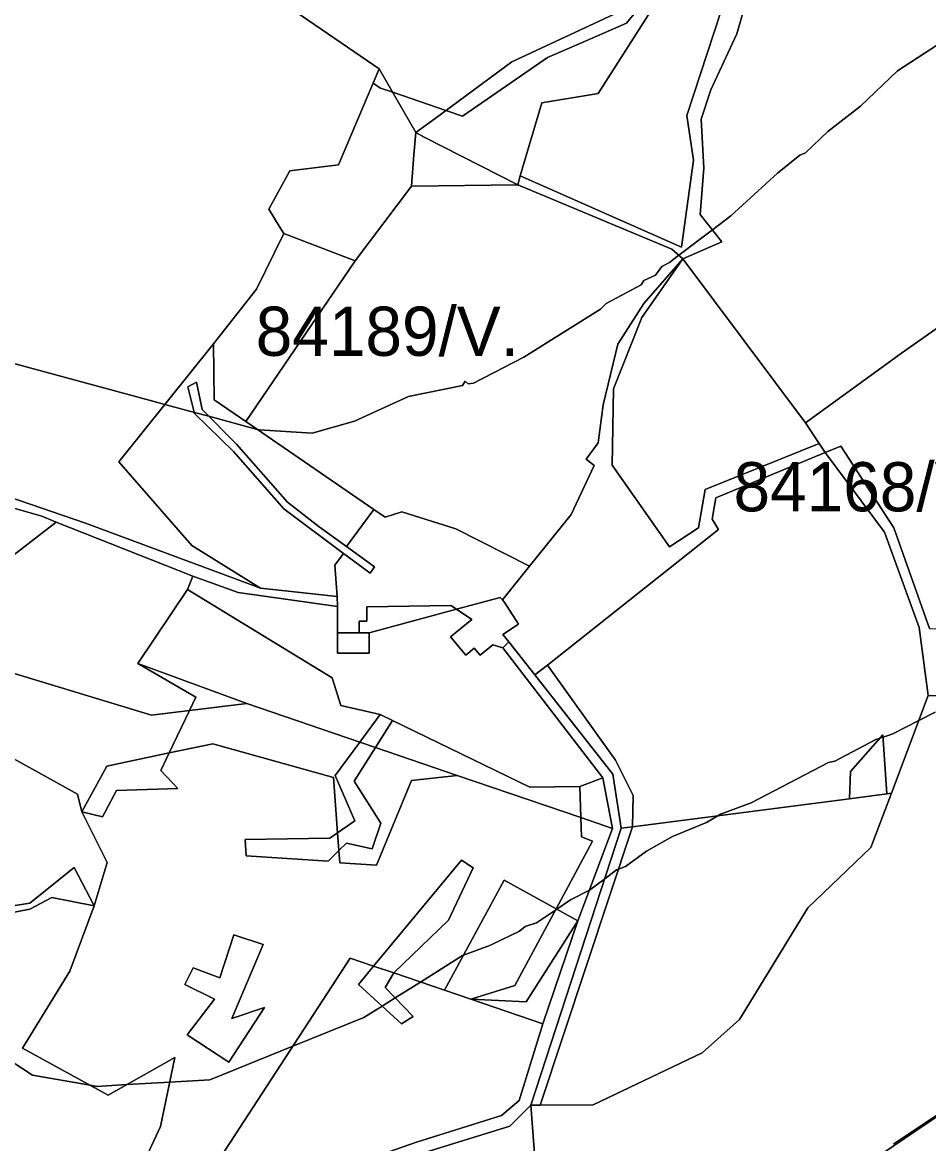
# Model space of a CAD drawing. Extents: x -477304 to -465429, y -1159113 to -1149210.
# Drawn here: x -472634.3 to -472357.9, y -1156987 to -1156645.1 of the extents above; entities that cross this region are included whole.
import ezdxf

# ---------------------------------------------------------------- set-up
doc = ezdxf.new("R2010")
doc.units = 0
for name, color, linetype in [('BPEJ_s', 7, 'Continuous'), ('ostatni_s', 7, 'Continuous'), ('PUPFL_s', 7, 'Continuous'), ('trav_porost_s', 7, 'Continuous'), ('zahrada_s', 7, 'Continuous')]:
    doc.layers.add(name, color=color, linetype=linetype)

msp = doc.modelspace()

# ---------------------------------------------------------------- linework, layer by layer
at = {"layer": 'BPEJ_s'}
for points in [[(-472441.7, -1156635.08), (-472450.07, -1156645.39), (-472463.76, -1156651.33), (-472474.1, -1156655.82), (-472486.64, -1156664.49), (-472500, -1156673.73), (-472505.12, -1156671.99), (-472521.34, -1156666.45), (-472525.09, -1156665.17), (-472526.28, -1156664.38), (-472527.3, -1156663.7), (-472525.43, -1156659.31), (-472554.72, -1156639.26)], [(-472554.72, -1156639.26), (-472525.43, -1156659.31), (-472527.3, -1156663.7), (-472526.28, -1156664.38), (-472525.09, -1156665.17), (-472521.34, -1156666.45), (-472505.12, -1156671.99), (-472500, -1156673.73), (-472486.64, -1156664.49), (-472474.1, -1156655.82), (-472463.76, -1156651.33), (-472450.07, -1156645.39), (-472441.7, -1156635.08)], [(-472662.1, -1156742.37), (-472594.52, -1156760.62), (-472590.83, -1156761.62), (-472581.83, -1156764.06), (-472577.42, -1156765.25), (-472562.69, -1156769.24), (-472562.09, -1156769.4), (-472545.87, -1156770.42), (-472533.03, -1156766.7), (-472516.48, -1156759.27), (-472500, -1156755.83), (-472499.2, -1156754.5), (-472498.35, -1156755.35), (-472496.64, -1156755.14), (-472481.33, -1156747.27), (-472457.94, -1156732.59), (-472456.24, -1156730.89), (-472445.6, -1156725.15), (-472444.75, -1156723.87), (-472441.14, -1156722.17), (-472439.22, -1156719.62), (-472436.96, -1156718.38), (-472434.05, -1156716.17), (-472423.83, -1156708.4), (-472418.17, -1156704.09), (-472403.92, -1156691.12), (-472397.11, -1156685.59), (-472395.41, -1156684.95), (-472388.6, -1156678.36), (-472378.61, -1156670.7), (-472367.34, -1156659.86), (-472355.21, -1156651.99)], [(-472355.21, -1156651.99), (-472367.34, -1156659.86), (-472378.61, -1156670.7), (-472388.6, -1156678.36), (-472395.41, -1156684.95), (-472397.11, -1156685.59), (-472403.92, -1156691.12), (-472418.17, -1156704.09), (-472423.83, -1156708.4), (-472434.05, -1156716.17), (-472436.96, -1156718.38), (-472439.22, -1156719.62), (-472441.14, -1156722.17), (-472444.75, -1156723.87), (-472445.6, -1156725.15), (-472456.24, -1156730.89), (-472457.94, -1156732.59), (-472481.33, -1156747.27), (-472496.64, -1156755.14), (-472498.35, -1156755.35), (-472499.2, -1156754.5), (-472500, -1156755.83), (-472516.48, -1156759.27), (-472533.03, -1156766.7), (-472545.87, -1156770.42), (-472562.09, -1156769.4), (-472562.69, -1156769.24), (-472577.42, -1156765.25), (-472581.83, -1156764.06), (-472590.83, -1156761.62), (-472594.52, -1156760.62), (-472662.1, -1156742.37)], [(-472116.37, -1156762.45), (-472135.94, -1156774.49), (-472198.26, -1156835.74), (-472215.96, -1156868.96), (-472217.19, -1156871.26), (-472218.74, -1156885.27), (-472220.16, -1156898.05), (-472220.17, -1156899.22), (-472220.24, -1156910.32), (-472246.54, -1156919.54), (-472276.74, -1156936.97), (-472303.41, -1156955.05), (-472309.06, -1156958.88), (-472333.73, -1156964.62), (-472337.14, -1156966.32), (-472354.15, -1156977.59), (-472368.61, -1156987.17)], [(-472135.94, -1156774.49), (-472198.26, -1156835.74), (-472215.96, -1156868.96), (-472217.19, -1156871.26), (-472218.74, -1156885.27), (-472220.16, -1156898.05), (-472220.17, -1156899.22), (-472220.24, -1156910.32), (-472246.54, -1156919.54), (-472276.74, -1156936.97), (-472303.41, -1156955.05), (-472309.06, -1156958.88), (-472333.73, -1156964.62), (-472337.14, -1156966.32), (-472354.15, -1156977.59), (-472368.61, -1156987.17)], [(-472355.85, -1156855.52), (-472360.86, -1156858.06), (-472368.83, -1156862.11), (-472370.52, -1156862.68), (-472371.78, -1156863.1), (-472372.19, -1156863.23), (-472372.7, -1156863.4), (-472373.93, -1156863.81), (-472386.48, -1156870.41), (-472388.39, -1156870.83), (-472412, -1156883.17), (-472421.36, -1156886.57), (-472422.19, -1156887.07), (-472425.61, -1156889.12), (-472436.03, -1156893.38), (-472443.9, -1156897.84), (-472450.28, -1156902.52), (-472452.45, -1156903.35), (-472453.05, -1156903.58), (-472456.68, -1156906.29), (-472461.32, -1156909.73), (-472467.08, -1156912.73), (-472471.28, -1156915.56), (-472471.67, -1156915.82), (-472477.5, -1156919.75), (-472480.91, -1156920.81), (-472482.61, -1156922.3), (-472491.11, -1156926.34), (-472492.06, -1156926.69), (-472499.7, -1156929.55), (-472500, -1156929.67), (-472512.87, -1156937.77), (-472520.56, -1156942.6), (-472524.57, -1156945.12), (-472530.16, -1156948.64), (-472551.8, -1156957.36), (-472577.12, -1156967.56), (-472589.32, -1156968.28), (-472602.4, -1156969.05), (-472611.59, -1156969.59)], [(-472422.19, -1156887.07), (-472421.36, -1156886.57), (-472412, -1156883.17), (-472388.39, -1156870.83), (-472386.48, -1156870.41), (-472373.93, -1156863.81), (-472372.7, -1156863.4), (-472372.19, -1156863.23), (-472371.78, -1156863.1), (-472370.52, -1156862.68), (-472368.83, -1156862.11), (-472360.86, -1156858.06), (-472355.85, -1156855.52)], [(-472640.98, -1156959.79), (-472631.18, -1156966.21), (-472613.63, -1156969.24), (-472611.59, -1156969.59), (-472602.4, -1156969.05), (-472589.32, -1156968.28), (-472577.12, -1156967.56), (-472551.8, -1156957.36), (-472530.16, -1156948.64), (-472524.57, -1156945.12), (-472520.56, -1156942.6), (-472512.87, -1156937.77), (-472500, -1156929.67), (-472499.7, -1156929.55), (-472492.06, -1156926.69), (-472491.11, -1156926.34), (-472482.61, -1156922.3), (-472480.91, -1156920.81), (-472477.5, -1156919.75), (-472471.67, -1156915.82), (-472471.28, -1156915.56), (-472467.08, -1156912.73), (-472461.32, -1156909.73), (-472456.68, -1156906.29), (-472453.05, -1156903.58), (-472452.45, -1156903.35), (-472450.28, -1156902.52), (-472443.9, -1156897.84), (-472436.03, -1156893.38), (-472425.61, -1156889.12), (-472422.19, -1156887.07)], [(-472611.59, -1156969.59), (-472613.63, -1156969.24), (-472631.18, -1156966.21), (-472640.98, -1156959.79)]]:
    msp.add_lwpolyline(points, dxfattribs=at)
at = {"layer": 'ostatni_s'}
for points in [[(-472532.82, -1156717.86), (-472566.14, -1156766.88), (-472575.82, -1156760.24), (-472576.01, -1156743.14), (-472562.87, -1156726.46), (-472554.55, -1156709.55)], [(-472583.78, -1156756.26), (-472581.17, -1156754.82), (-472579.43, -1156763.23), (-472568.95, -1156773.78), (-472553.46, -1156791.45), (-472543.79, -1156799), (-472535.43, -1156805), (-472526.87, -1156811.15), (-472528.16, -1156813.09), (-472533.27, -1156809.36), (-472536.38, -1156807.08), (-472554.52, -1156793.52), (-472569.91, -1156775.96), (-472581.75, -1156764.37)], [(-472357.62, -1156830), (-472352.97, -1156830.05), (-472351.8, -1156850.64), (-472357.97, -1156850.39), (-472360.81, -1156829.71), (-472371.34, -1156800.62), (-472389.42, -1156776.33), (-472384.69, -1156774.37), (-472368.5, -1156799.23)], [(-472531.53, -1156827.77), (-472531.54, -1156831.27), (-472538.14, -1156831.25), (-472538.12, -1156823.31), (-472538.32, -1156820.17), (-472539, -1156810.66), (-472536.38, -1156807.08), (-472533.27, -1156809.36), (-472528.16, -1156813.09), (-472526.87, -1156811.15), (-472535.43, -1156805), (-472527.1, -1156793.63), (-472523.6, -1156796.04), (-472518.57, -1156794.35), (-472502.12, -1156799.6), (-472479.61, -1156811), (-472487.86, -1156821.27), (-472488.56, -1156820.47), (-472501.86, -1156824.07), (-472503.6, -1156822.91), (-472529.23, -1156823.34), (-472529.25, -1156827.78)], [(-472528.54, -1156831.28), (-472531.54, -1156831.27), (-472531.53, -1156827.77), (-472529.25, -1156827.78), (-472529.23, -1156823.34), (-472503.6, -1156822.91), (-472501.86, -1156824.07)], [(-472499.07, -1156838.1), (-472503.66, -1156832.52), (-472497.18, -1156827.18), (-472501.86, -1156824.07), (-472488.56, -1156820.47), (-472487.86, -1156821.27), (-472487.34, -1156821.85), (-472482.93, -1156828.68), (-472487.71, -1156831.76), (-472485.9, -1156834.06), (-472487.76, -1156835.82), (-472490.82, -1156834.9), (-472494.67, -1156838.07), (-472496.44, -1156835.93)], [(-472528.56, -1156837.53), (-472538.16, -1156837.5), (-472538.14, -1156831.25), (-472531.54, -1156831.27), (-472528.54, -1156831.28)]]:
    msp.add_lwpolyline(points, close=True, dxfattribs=at)
for points in [[(-472648.53, -1156786.33), (-472615, -1156797.87), (-472561.62, -1156817.71), (-472538.32, -1156820.17), (-472538.12, -1156823.31), (-472568.42, -1156819.04), (-472582.32, -1156813.98), (-472624, -1156797.56), (-472628.39, -1156795.71), (-472647.71, -1156790.18)], [(-472548.47, -1156998.65), (-472514.05, -1156986.63), (-472488.17, -1156978.52), (-472482.8, -1156973.95), (-472475.52, -1156950.49), (-472464.82, -1156919.14), (-472454.27, -1156890.91), (-472457.23, -1156875.51), (-472487.76, -1156835.82), (-472485.9, -1156834.06), (-472477.97, -1156844.13), (-472454.24, -1156874.36), (-472451.66, -1156890.88), (-472479.18, -1156975.3), (-472485.63, -1156981.69), (-472512.56, -1156990.09)]]:
    msp.add_lwpolyline(points, dxfattribs=at)
at = {"layer": 'PUPFL_s'}
for points in [[(-472436.06, -1156618.15), (-472452.46, -1156641.98), (-472485.02, -1156657.15), (-472508.39, -1156674.4), (-472514.3, -1156678.76), (-472525.43, -1156659.31), (-472554.72, -1156639.26), (-472590.4, -1156625.83), (-472583.95, -1156534.35), (-472531.75, -1156522.28), (-472529.41, -1156526.79), (-472515.08, -1156528.87), (-472489.81, -1156543.28), (-472462.88, -1156546.83), (-472460.93, -1156553.43), (-472447.67, -1156591.44), (-472437.2, -1156615.54)], [(-472508.39, -1156674.4), (-472485.02, -1156657.15), (-472452.46, -1156641.98), (-472436.06, -1156618.15), (-472400.56, -1156584.81), (-472397.11, -1156583.52), (-472394.76, -1156582.64), (-472393.84, -1156583.61), (-472388.14, -1156589.63), (-472394.29, -1156598.74), (-472402.85, -1156601.83), (-472408.83, -1156604), (-472410.88, -1156604.47), (-472429.76, -1156618.89), (-472439.49, -1156636.61), (-472458.68, -1156666.86), (-472475.87, -1156669.7), (-472482.41, -1156691.96), (-472483.21, -1156694.68), (-472511.7, -1156680.09), (-472514.3, -1156678.76)], [(-472532.82, -1156717.86), (-472554.55, -1156709.55), (-472555.97, -1156707.24), (-472559.13, -1156702.14), (-472552.69, -1156690.37), (-472537.88, -1156688.58), (-472525.43, -1156659.31), (-472514.3, -1156678.76), (-472514.85, -1156685.5), (-472515.63, -1156695.03)], [(-472483.21, -1156694.68), (-472515.63, -1156695.03), (-472514.85, -1156685.5), (-472514.3, -1156678.76), (-472511.7, -1156680.09)], [(-472706.78, -1156867.02), (-472715.43, -1156871.86), (-472717.75, -1156866.96), (-472665.8, -1156829.71), (-472646.02, -1156814.49), (-472637.12, -1156843.61), (-472594.91, -1156856.41), (-472583.36, -1156855), (-472589.5, -1156867.9), (-472608.5, -1156871.93), (-472616.12, -1156885.89), (-472617.48, -1156880.47), (-472647.02, -1156864.09), (-472671.49, -1156885.37), (-472682.72, -1156870.62), (-472696.04, -1156876.51)], [(-472476.37, -1156975.29), (-472460.19, -1156975.26), (-472426.99, -1156959.38), (-472415.58, -1156949.24), (-472394.67, -1156915.11), (-472375.46, -1156896.76), (-472369.2, -1156880.22), (-472357.97, -1156850.39), (-472351.8, -1156850.64), (-472270.77, -1156853.98), (-472230.8, -1156865.95), (-472215.62, -1156866.51), (-472221.16, -1156906.32), (-472251.67, -1156919.39), (-472287.03, -1156938.71), (-472307.14, -1156958.77), (-472336.68, -1156966.17), (-472382.8, -1156997.43), (-472414.59, -1157035.96), (-472473.75, -1157053.08), (-472475.82, -1157019.69), (-472479.18, -1156975.3)], [(-472583.36, -1156855), (-472565.83, -1156852.87), (-472531.4, -1156864.64), (-472538.92, -1156874.83), (-472532.92, -1156888.62), (-472538.15, -1156892.29), (-472539.42, -1156875.41), (-472576.23, -1156865.09), (-472589.5, -1156867.9)], [(-472537.75, -1156897.66), (-472538.15, -1156892.29), (-472532.92, -1156888.62), (-472538.92, -1156874.83), (-472531.4, -1156864.64), (-472526.61, -1156866.28), (-472533.1, -1156876.57), (-472524.98, -1156889.34), (-472527.61, -1156897.18), (-472535.45, -1156895.39)], [(-472537.46, -1156901.45), (-472537.75, -1156897.66), (-472535.45, -1156895.39), (-472527.61, -1156897.18), (-472524.98, -1156889.34), (-472533.1, -1156876.57), (-472526.61, -1156866.28), (-472501.7, -1156874.79), (-472515.56, -1156876.3), (-472526.3, -1156902.18)], [(-472375.46, -1156896.76), (-472394.67, -1156915.11), (-472415.58, -1156949.24), (-472426.99, -1156959.38), (-472460.19, -1156975.26), (-472476.37, -1156975.29), (-472448.15, -1156890.43), (-472382.04, -1156881.88), (-472370.59, -1156880.4), (-472369.2, -1156880.22)], [(-472479.18, -1156975.3), (-472451.66, -1156890.88), (-472448.15, -1156890.43), (-472476.37, -1156975.29)], [(-472632.01, -1156915.58), (-472656.6, -1156920.34), (-472657.25, -1156917.68), (-472632.02, -1156913.73), (-472618.53, -1156902.87), (-472612.42, -1156914.59), (-472625.27, -1156912.02)], [(-472707.28, -1157125.61), (-472723.28, -1157131.37), (-472760.71, -1157130.4), (-472753.24, -1157123.49), (-472750.8, -1157125.46), (-472716.75, -1157116.55), (-472705.79, -1157108.09), (-472683.02, -1157097.79), (-472646.35, -1157067.59), (-472593.93, -1157027.42), (-472543.78, -1157001.28), (-472512.56, -1156990.09), (-472485.63, -1156981.69), (-472479.18, -1156975.3), (-472475.82, -1157019.69), (-472473.75, -1157053.08), (-472499.35, -1157059.5), (-472542.32, -1157097.74), (-472575.02, -1157101.39), (-472662.17, -1157111.11), (-472693.12, -1157120.63)]]:
    msp.add_lwpolyline(points, close=True, dxfattribs=at)
for points in [[(-472647.02, -1156864.09), (-472617.48, -1156880.47), (-472616.12, -1156885.89), (-472608.39, -1156901.31), (-472612.42, -1156914.59), (-472618.53, -1156902.87), (-472632.02, -1156913.73), (-472657.25, -1156917.68)], [(-472656.6, -1156920.34), (-472632.01, -1156915.58), (-472625.27, -1156912.02), (-472612.42, -1156914.59), (-472619.78, -1156934.51), (-472634.24, -1156957.92), (-472608.12, -1156972.26), (-472587.78, -1156960.84), (-472592.11, -1156981.8), (-472613.67, -1157028.18)], [(-472382.8, -1156997.43), (-472336.68, -1156966.17)]]:
    msp.add_lwpolyline(points, dxfattribs=at)
at = {"layer": 'trav_porost_s'}
for points in [[(-472227.65, -1156648.59), (-472366.12, -1156746.03), (-472395.47, -1156767.24), (-472432.86, -1156717.23), (-472420.96, -1156712.01), (-472427.52, -1156703.76), (-472426.47, -1156689.61), (-472427.29, -1156674.6), (-472424.28, -1156665.71), (-472416.34, -1156648.59), (-472402.85, -1156601.83), (-472394.29, -1156598.74), (-472391.67, -1156597.79), (-472373.99, -1156587.03), (-472357.34, -1156582.81)], [(-472660.7, -1156596.17), (-472629.98, -1156612.77), (-472590.4, -1156625.83), (-472554.72, -1156639.26), (-472525.43, -1156659.31), (-472537.88, -1156688.58), (-472552.69, -1156690.37), (-472559.13, -1156702.14), (-472555.97, -1156707.24), (-472554.55, -1156709.55), (-472562.87, -1156726.46), (-472576.01, -1156743.14), (-472604.86, -1156779.11), (-472582.6, -1156804.65), (-472561.62, -1156817.71), (-472615, -1156797.87), (-472648.53, -1156786.33)], [(-472357.62, -1156830), (-472368.5, -1156799.23), (-472384.69, -1156774.37), (-472389.42, -1156776.33), (-472391.29, -1156773.52), (-472395.47, -1156767.24), (-472366.12, -1156746.03), (-472227.65, -1156648.59)], [(-472613.67, -1157028.18), (-472592.11, -1156981.8), (-472587.78, -1156960.84), (-472608.12, -1156972.26), (-472634.24, -1156957.92), (-472619.78, -1156934.51), (-472612.42, -1156914.59), (-472608.39, -1156901.31), (-472616.12, -1156885.89), (-472609.87, -1156887.35), (-472605.6, -1156879.37), (-472586.85, -1156878.75), (-472592.04, -1156873.23), (-472589.5, -1156867.9), (-472576.23, -1156865.09), (-472539.42, -1156875.41), (-472538.15, -1156892.29), (-472540.49, -1156893.94), (-472566.35, -1156894.33), (-472566.07, -1156899.31), (-472540.99, -1156900.88), (-472537.75, -1156897.66), (-472537.46, -1156901.45), (-472526.3, -1156902.18), (-472515.56, -1156876.3), (-472501.7, -1156874.79), (-472463.95, -1156887.61), (-472463.76, -1156893.52), (-472460.37, -1156894.86), (-472471.47, -1156915.45), (-472487.29, -1156906.69), (-472505.51, -1156940.26), (-472520.99, -1156935.02), (-472504.28, -1156918.96), (-472496.82, -1156902.94), (-472500.35, -1156900.61), (-472527.17, -1156932.93), (-472534.32, -1156930.51), (-472594.99, -1157023.68)]]:
    msp.add_lwpolyline(points, dxfattribs=at)
for points in [[(-472416.34, -1156648.59), (-472424.28, -1156665.71), (-472427.29, -1156674.6), (-472426.47, -1156689.61), (-472427.52, -1156703.76), (-472420.96, -1156712.01), (-472432.86, -1156717.23), (-472436.15, -1156714.29), (-472483.21, -1156694.68), (-472482.41, -1156691.96), (-472433.2, -1156713.71), (-472429.61, -1156687.16), (-472431.62, -1156673.53), (-472408.83, -1156604), (-472402.85, -1156601.83)], [(-472429.76, -1156618.89), (-472410.88, -1156604.47), (-472408.83, -1156604), (-472431.62, -1156673.53), (-472429.61, -1156687.16), (-472433.2, -1156713.71), (-472482.41, -1156691.96), (-472475.87, -1156669.7), (-472458.68, -1156666.86), (-472439.49, -1156636.61)], [(-472479.61, -1156811), (-472502.12, -1156799.6), (-472518.57, -1156794.35), (-472523.6, -1156796.04), (-472527.1, -1156793.63), (-472566.14, -1156766.88), (-472532.82, -1156717.86), (-472515.63, -1156695.03), (-472483.21, -1156694.68), (-472436.15, -1156714.29), (-472432.86, -1156717.23), (-472444.69, -1156730.83), (-472452.68, -1156743.3), (-472457.18, -1156761.73), (-472458.62, -1156773.31), (-472462.3, -1156778.28), (-472459.86, -1156780.26), (-472466.92, -1156795.2)], [(-472428.06, -1156799.22), (-472426.01, -1156787.57), (-472391.29, -1156773.52), (-472389.42, -1156776.33), (-472422.75, -1156790.15), (-472423.88, -1156796.63), (-472421.99, -1156799.75), (-472474.13, -1156841.1), (-472477.97, -1156844.13), (-472485.9, -1156834.06), (-472487.71, -1156831.76), (-472482.93, -1156828.68), (-472487.34, -1156821.85), (-472487.86, -1156821.27), (-472479.61, -1156811), (-472466.92, -1156795.2), (-472459.86, -1156780.26), (-472462.3, -1156778.28), (-472458.62, -1156773.31), (-472457.18, -1156761.73), (-472452.68, -1156743.3), (-472444.69, -1156730.83), (-472432.86, -1156717.23), (-472445.34, -1156735.08), (-472453.96, -1156756.86), (-472454.41, -1156780.18), (-472436.92, -1156805.09)], [(-472453.96, -1156756.86), (-472445.34, -1156735.08), (-472432.86, -1156717.23), (-472395.47, -1156767.24), (-472391.29, -1156773.52), (-472426.01, -1156787.57), (-472428.06, -1156799.22), (-472436.92, -1156805.09), (-472454.41, -1156780.18)], [(-472647.71, -1156790.18), (-472628.39, -1156795.71), (-472624, -1156797.56), (-472646.02, -1156814.49), (-472646.75, -1156812.09), (-472703.3, -1156789.75), (-472743.69, -1156802.97), (-472755.86, -1156772), (-472768.63, -1156737.77), (-472756.56, -1156740.03), (-472702.29, -1156727.7), (-472699.04, -1156738.07), (-472748.89, -1156750.88), (-472739.58, -1156780.71), (-472727.2, -1156796.24), (-472719.8, -1156783.38), (-472715.66, -1156789.92), (-472708.02, -1156781.45), (-472706, -1156785.51), (-472681.08, -1156772.77), (-472690.06, -1156758.54), (-472678.61, -1156771.32)], [(-472422.75, -1156790.15), (-472389.42, -1156776.33), (-472371.34, -1156800.62), (-472360.81, -1156829.71), (-472357.97, -1156850.39), (-472369.2, -1156880.22), (-472370.59, -1156880.4), (-472371.83, -1156862.42), (-472381.69, -1156873.58), (-472382.04, -1156881.88), (-472448.15, -1156890.43), (-472448, -1156880.91), (-472453.42, -1156870.14), (-472474.13, -1156841.1), (-472421.99, -1156799.75), (-472423.88, -1156796.63)], [(-472581.39, -1156850.87), (-472583.36, -1156855), (-472594.91, -1156856.41), (-472637.12, -1156843.61), (-472646.02, -1156814.49), (-472624, -1156797.56), (-472582.32, -1156813.98), (-472583.92, -1156818.05), (-472599.06, -1156840.67)], [(-472525.18, -1156856.21), (-472537.12, -1156853.49), (-472539.76, -1156845.03), (-472583.92, -1156818.05), (-472582.32, -1156813.98), (-472568.42, -1156819.04), (-472538.12, -1156823.31), (-472538.14, -1156831.25), (-472538.16, -1156837.5), (-472528.56, -1156837.53), (-472528.54, -1156831.28), (-472501.86, -1156824.07), (-472497.18, -1156827.18), (-472503.66, -1156832.52), (-472499.07, -1156838.1), (-472496.44, -1156835.93), (-472494.67, -1156838.07), (-472490.82, -1156834.9), (-472487.76, -1156835.82), (-472457.23, -1156875.51), (-472464.26, -1156878.18), (-472479.51, -1156878.4), (-472521.41, -1156858.04)], [(-472583.92, -1156818.05), (-472539.76, -1156845.03), (-472537.12, -1156853.49), (-472525.18, -1156856.21), (-472531.4, -1156864.64), (-472565.83, -1156852.87), (-472599.06, -1156840.67)], [(-472565.83, -1156852.87), (-472583.36, -1156855), (-472581.39, -1156850.87), (-472599.06, -1156840.67)], [(-472448.15, -1156890.43), (-472451.66, -1156890.88), (-472454.24, -1156874.36), (-472477.97, -1156844.13), (-472474.13, -1156841.1), (-472453.42, -1156870.14), (-472448, -1156880.91)], [(-472526.61, -1156866.28), (-472531.4, -1156864.64), (-472525.18, -1156856.21), (-472521.41, -1156858.04)], [(-472521.41, -1156858.04), (-472479.51, -1156878.4), (-472464.26, -1156878.18), (-472463.95, -1156887.61), (-472501.7, -1156874.79), (-472526.61, -1156866.28)], [(-472370.59, -1156880.4), (-472382.04, -1156881.88), (-472381.69, -1156873.58), (-472371.83, -1156862.42)], [(-472616.12, -1156885.89), (-472608.5, -1156871.93), (-472589.5, -1156867.9), (-472592.04, -1156873.23), (-472586.85, -1156878.75), (-472605.6, -1156879.37), (-472609.87, -1156887.35)], [(-472457.23, -1156875.51), (-472454.27, -1156890.91), (-472463.95, -1156887.61), (-472464.26, -1156878.18)], [(-472464.82, -1156919.14), (-472471.47, -1156915.45), (-472460.37, -1156894.86), (-472463.76, -1156893.52), (-472463.95, -1156887.61), (-472454.27, -1156890.91)], [(-472540.49, -1156893.94), (-472538.15, -1156892.29), (-472537.75, -1156897.66), (-472540.99, -1156900.88), (-472566.07, -1156899.31), (-472566.35, -1156894.33)], [(-472520.99, -1156935.02), (-472527.17, -1156932.93), (-472500.35, -1156900.61), (-472496.82, -1156902.94), (-472504.28, -1156918.96)], [(-472484.1, -1156938.87), (-472497.53, -1156942.98), (-472505.51, -1156940.26), (-472487.29, -1156906.69), (-472471.47, -1156915.45)], [(-472471.47, -1156915.45), (-472464.82, -1156919.14), (-472480.66, -1156943.83), (-472497.53, -1156942.98), (-472484.1, -1156938.87)], [(-472464.82, -1156919.14), (-472475.52, -1156950.49), (-472497.53, -1156942.98), (-472480.66, -1156943.83)], [(-472575.67, -1156943.03), (-472583.98, -1156953.87), (-472571.36, -1156962.18), (-472560.42, -1156945.57), (-472570.44, -1156948.93), (-472560.83, -1156926.38), (-472569.76, -1156923.41), (-472574.1, -1156936.52), (-472582.22, -1156933.41), (-472584.72, -1156938.57)], [(-472574.1, -1156936.52), (-472569.76, -1156923.41), (-472560.83, -1156926.38), (-472570.44, -1156948.93), (-472560.42, -1156945.57), (-472571.36, -1156962.18), (-472583.98, -1156953.87), (-472575.67, -1156943.03), (-472584.72, -1156938.57), (-472582.22, -1156933.41)], [(-472488.17, -1156978.52), (-472514.05, -1156986.63), (-472548.47, -1156998.65), (-472594.99, -1157023.68), (-472534.32, -1156930.51), (-472527.17, -1156932.93), (-472531.76, -1156938.49), (-472518.65, -1156950.57), (-472515.08, -1156948.24), (-472523.63, -1156939.44), (-472520.99, -1156935.02), (-472505.51, -1156940.26), (-472497.53, -1156942.98), (-472475.52, -1156950.49), (-472482.8, -1156973.95)], [(-472527.17, -1156932.93), (-472520.99, -1156935.02), (-472523.63, -1156939.44), (-472515.08, -1156948.24), (-472518.65, -1156950.57), (-472531.76, -1156938.49)]]:
    msp.add_lwpolyline(points, close=True, dxfattribs=at)
at = {"layer": 'zahrada_s'}
msp.add_lwpolyline([(-472581.75, -1156764.37), (-472569.91, -1156775.96), (-472554.52, -1156793.52), (-472536.38, -1156807.08), (-472539, -1156810.66), (-472538.32, -1156820.17), (-472561.62, -1156817.71), (-472582.6, -1156804.65), (-472604.86, -1156779.11), (-472576.01, -1156743.14), (-472575.82, -1156760.24), (-472566.14, -1156766.88), (-472527.1, -1156793.63), (-472535.43, -1156805), (-472543.79, -1156799), (-472553.46, -1156791.45), (-472568.95, -1156773.78), (-472579.43, -1156763.23), (-472581.17, -1156754.82), (-472583.78, -1156756.26)], close=True, dxfattribs=at)

# ---------------------------------------------------------------- texts
at = {"layer": 'BPEJ_s'}
for s, p in [('84189/V.', (-472563.12, -1156746.82)), ('84168/V.', (-472417.38, -1156794.24))]:
    msp.add_text(s, height=15, dxfattribs=at).set_placement(p)

doc.saveas('drawing.dxf')
